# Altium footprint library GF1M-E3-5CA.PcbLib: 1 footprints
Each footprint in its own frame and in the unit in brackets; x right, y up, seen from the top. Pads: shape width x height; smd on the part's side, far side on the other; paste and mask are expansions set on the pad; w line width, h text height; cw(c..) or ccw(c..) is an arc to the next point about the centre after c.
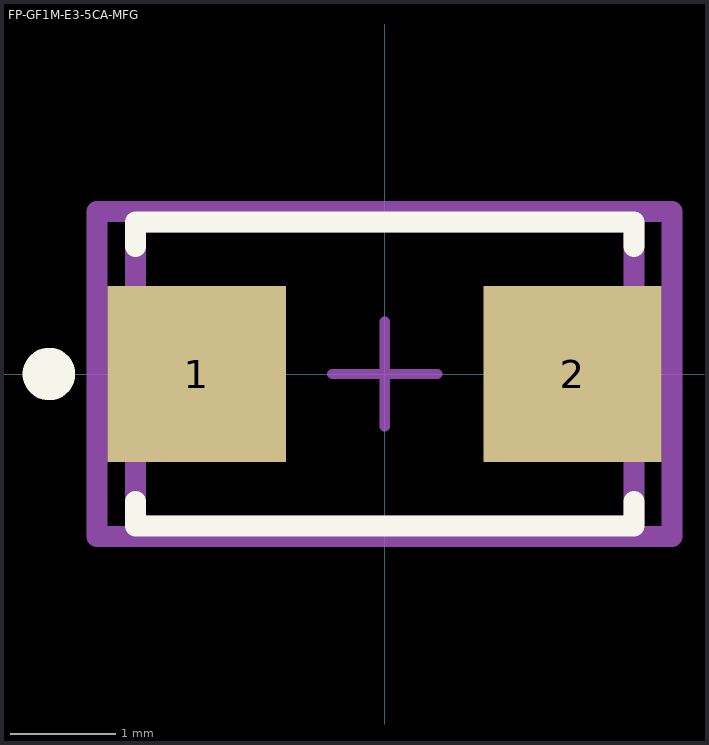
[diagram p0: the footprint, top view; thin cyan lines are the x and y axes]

## FP-GF1M-E3-5CA-MFG [mm]
pads (2):
  rect 1.7x1.68 smd paste+0 mask+0: 1(-1.79,0) 2(1.79,0)
Top Overlay:
  circle w0.25: c-3.2,0 r0.125
  lines w0.2: -2.375,-1.215 -2.375,-1.45 2.375,-1.45 2.375,-1.215 ; -2.375,1.215 -2.375,1.45 2.375,1.45 2.375,1.215
Top Assembly:
  lines w0.2: -2.74,-1.55 -2.74,1.55 2.74,1.55 2.74,-1.55 -2.74,-1.55
  text ".Designator" at 0,0.188 h1
Top 3D Body:
  lines w0.2: -2.375,-1.45 -2.375,1.45 2.375,1.45 2.375,-1.45 -2.375,-1.45
Top Courtyard:
  lines w0.2: -2.74,-1.55 -2.74,1.55 2.74,1.55 2.74,-1.55 -2.74,-1.55
Top Component Center:
  lines w0.1: -0.5,0 0.5,0 ; 0,-0.5 0,0.5
3D body "Diode_Vishay_GF1M-E3-5CA_eec.STEP": height 0.25, standoff 0, extent -2.74,-1.55 2.74,1.55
